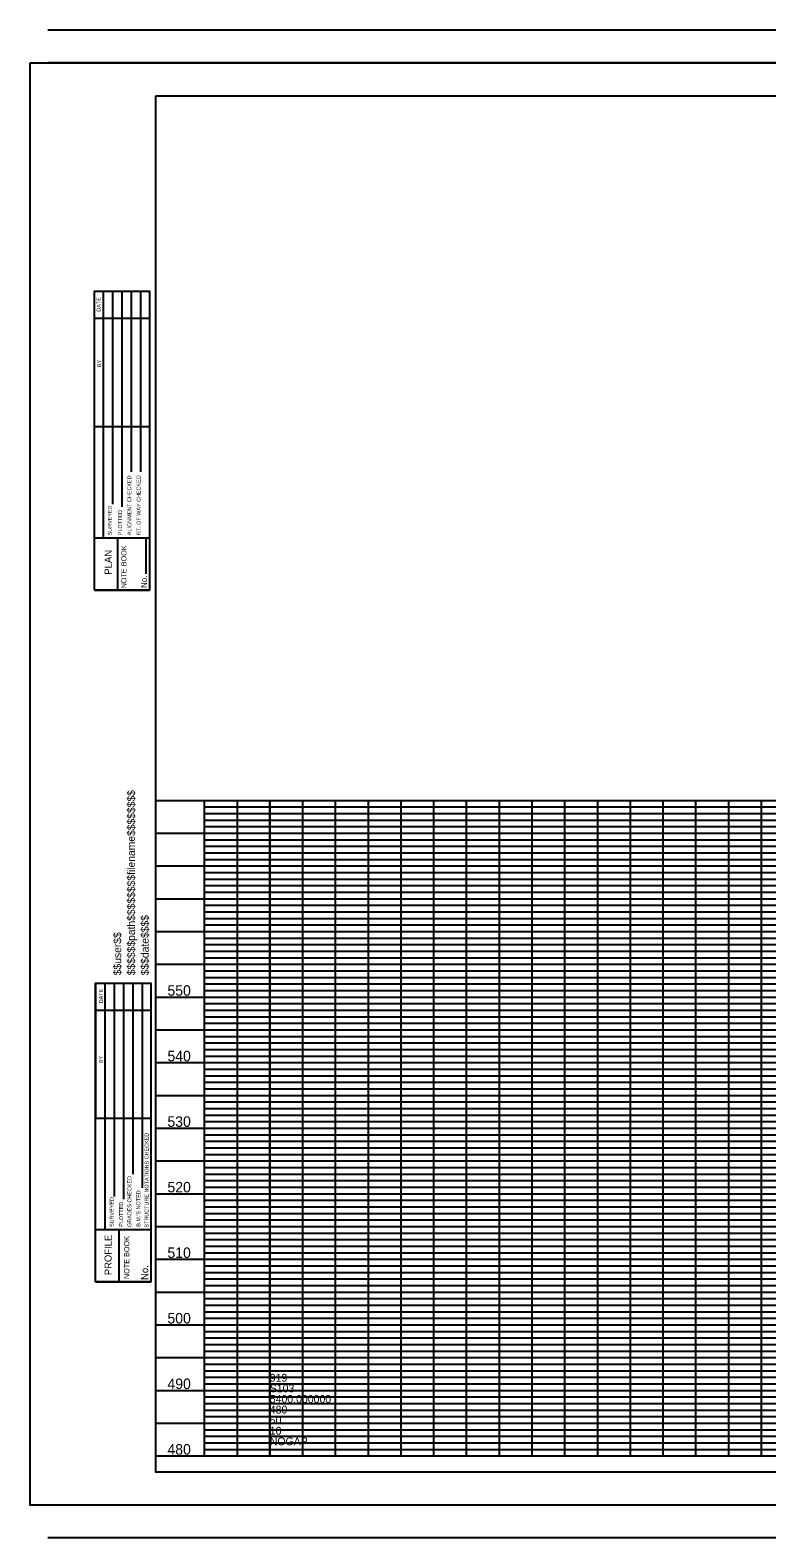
# Model space of a CAD drawing. Extents: x 49817 to 52200, y 49938 to 51088.
# Drawn here: x 49817 to 50379, y 49938 to 51088 of the extents above; entities that cross this region are included whole.
import ezdxf

# ---------------------------------------------------------------- set-up
doc = ezdxf.new("R2010")
doc.units = 0
for name, color, linetype in [('RD_DDB_ElevTX', 7, 'Continuous'), ('RD_GPK_Profile_Cell', 7, 'Continuous'), ('RD_SHT_Bndy', 7, 'Continuous'), ('RD_SHT_ID', 7, 'Continuous'), ('RD_SHT_Iplotshp', 7, 'Continuous'), ('RD_SHT_MjGrid', 7, 'Continuous'), ('RD_SHT_MnGrid', 7, 'Continuous'), ('RD_SHT_SubGrid', 7, 'Continuous'), ('RD_SHT_TX', 7, 'Continuous')]:
    doc.layers.add(name, color=color, linetype=linetype)

msp = doc.modelspace()

# ---------------------------------------------------------------- linework, layer by layer
at = {"layer": 'RD_GPK_Profile_Cell'}
for q in [(50000, 50500), (52200, 50000), (50000, 50000)]:
    msp.add_line((50000, 50000), q, dxfattribs=at)
at = {"layer": 'RD_SHT_Bndy'}
for p, q in [((51590.7, 51087.5), (49830.7, 51087.5)), ((51590.7, 51062.5), (49830.7, 51062.5)), ((49866.1, 50785.1), (49866.1, 50888.3)), ((49873.2, 50700.4), (49873.2, 50888.3)), ((49880.2, 50726), (49880.2, 50888.3)), ((49887.3, 50723.8), (49887.3, 50888.3)), ((49894.4, 50750.7), (49894.4, 50888.3)), ((49901.5, 50750.7), (49901.5, 50888.3)), ((49866.1, 50867.7), (49908.1, 50867.7)), ((49866.1, 50785.1), (49908.1, 50785.1)), ((49866.1, 50700.3), (49908.1, 50700.3)), ((49884.1, 50660.3), (49884.1, 50700.3)), ((49905.6, 50672.8), (49905.6, 50700.3)), ((49866.1, 50660.3), (49908.1, 50660.3)), ((49913, 50500), (51588, 50500)), ((49950, 50500), (49950, 50000)), ((49867.1, 50360.7), (49867.1, 50257.5)), ((49874.2, 50360.7), (49874.2, 50172.8)), ((49881.2, 50360.7), (49881.2, 50197.8)), ((49888.3, 50360.7), (49888.3, 50195.8)), ((49895.4, 50360.7), (49895.4, 50214.9)), ((49902.5, 50360.7), (49902.5, 50204.4)), ((49867.1, 50340.1), (49909.1, 50340.1)), ((49867.1, 50257.5), (49909.1, 50257.5)), ((49867.1, 50172.7), (49909.1, 50172.7)), ((49867.1, 50132.7), (49867.1, 50172.7)), ((49885.1, 50132.7), (49885.1, 50172.7)), ((49867.1, 50132.7), (49909.1, 50132.7)), ((49913, 50000), (51588, 50000)), ((51590.7, 49962.5), (49830.7, 49962.5)), ((51590.7, 49937.5), (49830.7, 49937.5))]:
    msp.add_line(p, q, dxfattribs=at)
for points in [[(49913.1, 51037.5), (51588, 51037.5), (51588, 49987.5), (49913.1, 49987.5)], [(49866.1, 50660.3), (49866.1, 50888.3), (49908.1, 50888.3), (49908.1, 50660.3)], [(49867.1, 50132.7), (49867.1, 50360.7), (49909.1, 50360.7), (49909.1, 50132.7)]]:
    msp.add_lwpolyline(points, close=True, dxfattribs=at)
at = {"layer": 'RD_SHT_Iplotshp'}
msp.add_lwpolyline([(49817.1, 51062.5), (51613, 51062.5), (51613, 49962.5), (49817.1, 49962.5)], close=True, dxfattribs=at)
at = {"layer": 'RD_SHT_MjGrid'}
for p, q in [((50000, 50500), (50000, 50000)), ((50050, 50500), (50050, 50000)), ((50100, 50500), (50100, 50000)), ((50150, 50500), (50150, 50000)), ((50200, 50500), (50200, 50000)), ((50250, 50500), (50250, 50000)), ((50300, 50500), (50300, 50000)), ((50350, 50500), (50350, 50000)), ((49913, 50450), (51588, 50450)), ((49913, 50400), (51588, 50400)), ((49913, 50350), (51588, 50350)), ((49913, 50300), (51588, 50300)), ((49913, 50250), (51588, 50250)), ((49913, 50200), (51588, 50200)), ((49913, 50150), (51588, 50150)), ((49913, 50100), (51588, 50100)), ((49913, 50050), (51588, 50050))]:
    msp.add_line(p, q, dxfattribs=at)
at = {"layer": 'RD_SHT_MnGrid'}
for p, q in [((49975, 50500), (49975, 50000)), ((50025, 50500), (50025, 50000)), ((50075, 50500), (50075, 50000)), ((50125, 50500), (50125, 50000)), ((50175, 50500), (50175, 50000)), ((50225, 50500), (50225, 50000)), ((50275, 50500), (50275, 50000)), ((50325, 50500), (50325, 50000)), ((50375, 50500), (50375, 50000)), ((49913, 50475), (51588, 50475)), ((49913, 50425), (51588, 50425)), ((49913, 50375), (51588, 50375)), ((49913, 50325), (51588, 50325)), ((49913, 50275), (51588, 50275)), ((49913, 50225), (51588, 50225)), ((49913, 50175), (51588, 50175)), ((49913, 50125), (51588, 50125)), ((49913, 50075), (51588, 50075)), ((49913, 50025), (51588, 50025))]:
    msp.add_line(p, q, dxfattribs=at)
at = {"layer": 'RD_SHT_SubGrid'}
for p, q in [((49950.1, 50495), (51549.8, 50495)), ((49950.1, 50490), (51549.3, 50490)), ((49950.1, 50485), (51549.8, 50485)), ((49950.1, 50480), (51549.8, 50480)), ((49950.1, 50470), (51549.8, 50470)), ((49950.1, 50465), (51548.8, 50465)), ((49950.1, 50460), (51549.3, 50460)), ((49950.1, 50455), (51549.8, 50455)), ((49950.1, 50445), (51549.8, 50445)), ((49950.1, 50440), (51549.8, 50440)), ((49950.1, 50435), (51549.3, 50435)), ((49950.1, 50430), (51549.8, 50430)), ((49950.1, 50420), (51548.8, 50420)), ((49950.1, 50415), (51548.8, 50415)), ((49950.1, 50410), (51549.3, 50410)), ((49950.1, 50405), (51549.3, 50405)), ((49950.1, 50395), (51548.8, 50395)), ((49950.1, 50390), (51549.3, 50390)), ((49950.1, 50385), (51548.8, 50385)), ((49950.1, 50380), (51549.8, 50380)), ((49950.1, 50370), (51549.3, 50370)), ((49950.1, 50365), (51549.3, 50365)), ((49950.1, 50360), (51549.3, 50360)), ((49950.1, 50355), (51549.3, 50355)), ((49950.2, 50345), (51548.8, 50345)), ((49950.2, 50340), (51548.8, 50340)), ((49950.1, 50335), (51549.3, 50335)), ((49950.1, 50330), (51549.3, 50330)), ((49950.1, 50320), (51549.3, 50320)), ((49950.1, 50315), (51549.3, 50315)), ((49950.1, 50310), (51548.8, 50310)), ((49950.1, 50305), (51549.3, 50305)), ((49950.1, 50305), (51549.3, 50305)), ((49950.1, 50295), (51549.8, 50295)), ((49950.1, 50290), (51549.8, 50290)), ((49950.1, 50285), (51549.8, 50285)), ((49950.1, 50280), (51549.8, 50280)), ((49950.1, 50270), (51549.8, 50270)), ((49950.1, 50265), (51549.8, 50265)), ((49950.1, 50260), (51549.8, 50260)), ((49950.1, 50255), (51549.8, 50255)), ((49950.1, 50245), (51549.9, 50245)), ((49950.1, 50240), (51549.9, 50240)), ((49950.1, 50235), (51549.9, 50235)), ((49950.1, 50230), (51549.9, 50230)), ((49950.1, 50220), (51549.9, 50220)), ((49950.1, 50215), (51549.9, 50215)), ((49950.1, 50210), (51549.9, 50210)), ((49950.1, 50205), (51549.9, 50205)), ((49950.1, 50195), (51549.9, 50195)), ((49950.1, 50190), (51549.9, 50190)), ((49950.1, 50185), (51549.9, 50185)), ((49950.1, 50180), (51549.9, 50180)), ((49950.1, 50170), (51549.9, 50170)), ((49950.1, 50170), (51549.9, 50170)), ((49950.1, 50165), (51549.9, 50165)), ((49950.1, 50160), (51549.6, 50160)), ((49950.1, 50155), (51549.6, 50155)), ((49950.1, 50145), (51549.8, 50145)), ((49950.1, 50140), (51550, 50140)), ((49950.1, 50135), (51550, 50135)), ((49950.1, 50130), (51550, 50130)), ((49950.1, 50120), (51550, 50120)), ((49950.1, 50115), (51550, 50115)), ((49950.1, 50110), (51550, 50110)), ((49950.1, 50105), (51550, 50105)), ((49950.1, 50095), (51550, 50095)), ((49950.1, 50090), (51550, 50090)), ((49950.1, 50085), (51550, 50085)), ((49950.1, 50080), (51549.9, 50080)), ((49950.1, 50070), (51549.6, 50070)), ((49950.1, 50065), (51549.9, 50065)), ((49950.1, 50060), (51549.9, 50060)), ((49950.1, 50055), (51549.9, 50055)), ((49950.1, 50040), (51549.9, 50040)), ((49950.2, 50045), (51549.9, 50045)), ((49950.1, 50035), (51549.9, 50035)), ((49950.1, 50030), (51549.9, 50030)), ((49950.2, 50020), (51549.9, 50020)), ((49950.2, 50015), (51549.9, 50015)), ((49950.2, 50010), (51549.9, 50010)), ((49950.2, 50005), (51549.9, 50005))]:
    msp.add_line(p, q, dxfattribs=at)

# ---------------------------------------------------------------- texts
at = {"layer": 'RD_DDB_ElevTX'}
for s, p in [('550', (49921.9, 50351)), ('540', (49921.9, 50301)), ('540', (49921.9, 50301)), ('540', (49921.9, 50301)), ('530', (49921.9, 50251)), ('530', (49921.9, 50251)), ('530', (49921.9, 50251)), ('520', (49921.9, 50201)), ('520', (49921.9, 50201)), ('520', (49921.9, 50201)), ('510', (49921.9, 50151)), ('510', (49921.9, 50151)), ('510', (49921.9, 50151)), ('500', (49921.9, 50101)), ('500', (49921.9, 50101)), ('500', (49921.9, 50101)), ('490', (49921.9, 50051)), ('490', (49921.9, 50051)), ('490', (49921.9, 50051)), ('480', (49921.9, 50001)), ('480', (49921.9, 50001)), ('480', (49921.9, 50001))]:
    msp.add_text(s, height=8, dxfattribs=at).set_placement(p)
at = {"layer": 'RD_GPK_Profile_Cell'}
for s, p in [('919', (50000, 50056.6)), ('S103', (50000, 50048.5)), ('480', (50000, 50032.3)), ('5400.000000', (50000, 50040.4)), ('50', (50000, 50024.2)), ('10', (50000, 50016.2)), ('NOGAP', (50000, 50008.1))]:
    msp.add_text(s, height=6, dxfattribs=at).set_placement(p)
at = {"layer": 'RD_SHT_ID'}
for s, p in [('$$$$$$path$$$$$$$$filename$$$$$$$$', (49897.1, 50366.6)), ('$$$date$$$$', (49907.6, 50366.6)), ('$$user$$', (49886.6, 50366.6))]:
    msp.add_text(s, height=5.88, rotation=90, dxfattribs=at).set_placement(p)
at = {"layer": 'RD_SHT_TX'}
for s, height, p in [('DATE', 3, (49870.9, 50872.8)), ('BY', 3, (49871.3, 50830.5)), ('ALIGNMENT CHECKED', 3, (49894.3, 50702.3)), ('RT. OF WAY CHECKED', 3, (49901.4, 50702.4)), ('SURVEYED', 3, (49879.4, 50702.1)), ('PLOTTED', 3, (49887.2, 50702.3)), ('NOTE BOOK', 4, (49890.6, 50661.7)), ('PLAN', 5.4, (49879.3, 50672.2)), ('No.', 4.5, (49906.2, 50662)), ('DATE', 3, (49872.7, 50345.2)), ('BY', 3, (49872.7, 50299.5)), ('STRUCTURE NOTATIONS CHECKED', 3, (49907.5, 50174.2)), ('GRADES CHECKED', 3, (49894.4, 50174.6)), ("B.M.'S NOTED", 3, (49901.2, 50174.8)), ('SURVEYED', 3, (49880.9, 50174.6)), ('PLOTTED', 3, (49888, 50174.7)), ('PROFILE', 5.4, (49879.3, 50137.8)), ('NOTE BOOK', 4, (49892.8, 50134.9)), ('No.', 5.4, (49907.2, 50134.2))]:
    msp.add_text(s, height=height, rotation=90, dxfattribs=at).set_placement(p)

doc.saveas('drawing.dxf')
